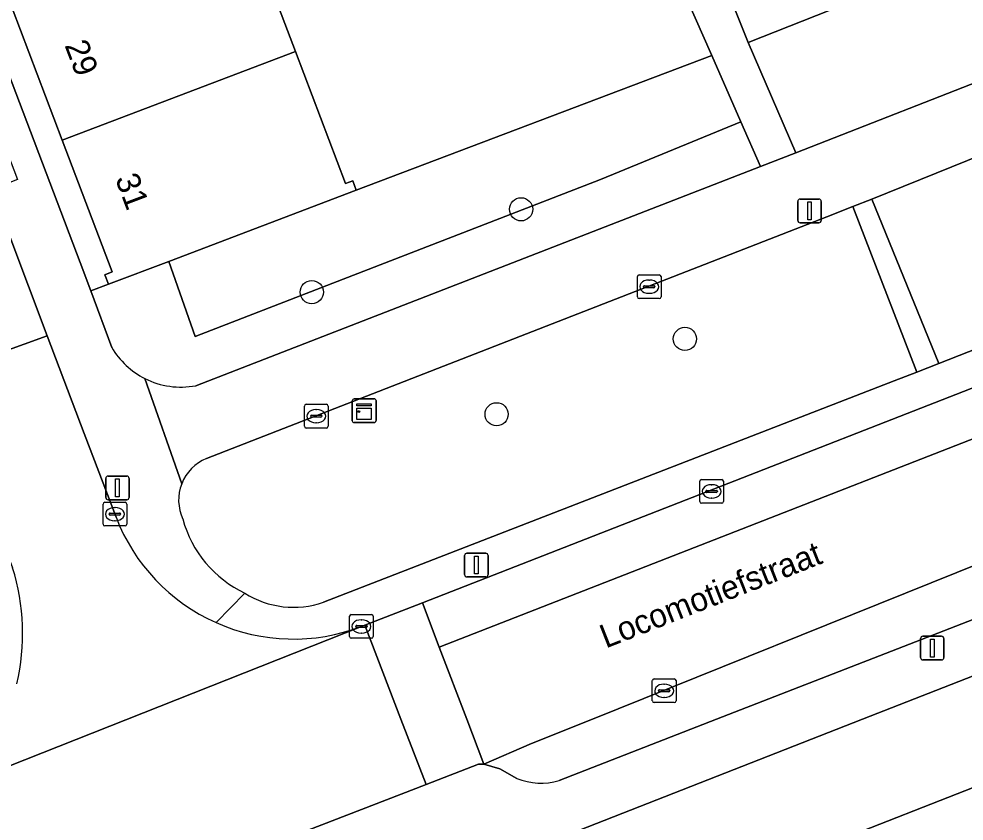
# Model space of a CAD drawing. Extents: x 162989 to 165008, y 383432 to 384338.
# Drawn here: x 163944.51 to 163984.37, y 383995.71 to 384029.53 of the extents above; entities that cross this region are included whole.
import ezdxf

# ---------------------------------------------------------------- set-up
doc = ezdxf.new("R2010")
doc.units = 0
for name, color, linetype in [('IMGEO_Boom', 7, 'Continuous'), ('IMGEO_Erf', 7, 'Continuous'), ('IMGEO_Groenvoorziening', 7, 'Continuous'), ('IMGEO_Kast', 7, 'Continuous'), ('IMGEO_Kolk', 7, 'Continuous'), ('IMGEO_Lichtmast', 7, 'Continuous'), ('IMGEO_Openbare_ruimte_label', 7, 'Continuous'), ('IMGEO_Pand', 7, 'Continuous'), ('IMGEO_Pand_nummerreeks', 7, 'Continuous'), ('IMGEO_Parkeervlak_open', 7, 'Continuous'), ('IMGEO_Rijbaan_lokaal_open', 7, 'Continuous'), ('IMGEO_Voetpad_open', 7, 'Continuous')]:
    doc.layers.add(name, color=color, linetype=linetype)

msp = doc.modelspace()

# ---------------------------------------------------------------- linework, layer by layer
at = {"layer": 'IMGEO_Boom'}
for centre in [(163965.69, 384021.504), (163956.864, 384018.013), (163972.597, 384016.041), (163964.657, 384012.862)]:
    msp.add_circle(centre, 0.489, dxfattribs=at)
at = {"layer": 'IMGEO_Erf'}
for points in [[(163943.537, 384061.532), (163945.643, 384055.968), (163947.749, 384050.405), (163949.856, 384044.841), (163951.962, 384039.278), (163954.068, 384033.715), (163956.175, 384028.151), (163958.279, 384022.593), (163958.588, 384022.709), (163958.74, 384022.307), (163973.729, 384027.989), (163972.384, 384031.053), (163969.628, 384036.532), (163967.145, 384041.315), (163965.004, 384045.848), (163957.177, 384062.593), (163954.16, 384068.424), (163952.82, 384071.014), (163951.255, 384074.041), (163946.04, 384085.093), (163944.693, 384087.722), (163943.187, 384090.664)], [(163932.033, 384058.943), (163947.096, 384019.256), (163947.541, 384018.062), (163948.288, 384018.345), (163948.138, 384018.748), (163948.445, 384018.863), (163946.338, 384024.426), (163944.232, 384029.99)], [(164010.509, 384011.664), (164000, 384007.793), (163980.091, 384000), (163962.348, 383993.055), (163960.87, 383992.07)], [(163960.66, 383990.018), (163961.435, 383987.966), (163967.123, 383990.2), (163973.139, 383992.563), (163978.985, 383994.86), (163984.797, 383997.143), (163990.831, 383999.513), (163992.07, 384000), (163996.693, 384001.816), (164000, 384003.115), (164002.477, 384004.075), (164008.327, 384006.341), (164014.738, 384008.825), (164014.172, 384010.446)]]:
    msp.add_lwpolyline(points, dxfattribs=at)
msp.add_lwpolyline([(163995.874, 384031.308), (163992.218, 384040.299), (163991.312, 384039.94), (163993.038, 384035.589), (163986.845, 384033.132), (163981.036, 384030.827), (163975.26, 384028.535), (163977.276, 384023.891), (163986.262, 384027.399)], close=True, dxfattribs=at)
at = {"layer": 'IMGEO_Groenvoorziening'}
for points in [[(163974.955, 384025.194), (163973.729, 384027.989), (163958.74, 384022.307), (163950.832, 384019.309), (163951.951, 384016.142), (163969.036, 384022.762)], [(163994.981, 384027.789), (163994.701, 384027.673), (163980.488, 384021.938), (163983.3, 384015), (163997.388, 384020.537), (163997.779, 384020.691)]]:
    msp.add_lwpolyline(points, close=True, dxfattribs=at)
for points in [[(163951.966, 384014.066), (163975.782, 384023.308), (163974.955, 384025.194), (163969.036, 384022.762), (163951.951, 384016.142), (163950.832, 384019.309)], [(163981.426, 384014.275), (163982.379, 384014.644), (163979.681, 384021.62), (163978.582, 384021.186), (163952.42, 384010.995)], [(163950.832, 384019.309), (163948.288, 384018.345), (163947.541, 384018.062), (163948.429, 384015.677)], [(163957.353, 384004.941), (163981.426, 384014.275)]]:
    msp.add_lwpolyline(points, dxfattribs=at)
for centre, radius, start, end in [((163951.344, 384017.387), 3.379, 210.3945, 243.2515), ((163951.342, 384017.383), 3.375, 243.251, 280.6535), ((163953.155, 384009.236), 1.907, 112.6714, 158.5818), ((163953.158, 384009.235), 1.91, 158.6017, 204.4051), ((163956.116, 384009.726), 4.868, 195.2427, 244.7463), ((163956.086, 384008.512), 3.789, 237.3085, 289.5408)]:
    msp.add_arc(centre, radius, start, end, dxfattribs=at)
at = {"layer": 'IMGEO_Kast'}
for p, q in [((163958.647, 384013.511), (163959.488, 384013.511)), ((163959.488, 384013.511), (163958.647, 384013.511)), ((163958.572, 384012.586), (163958.572, 384013.427)), ((163958.572, 384013.427), (163958.572, 384012.586)), ((163959.572, 384013.436), (163959.572, 384012.595)), ((163959.572, 384012.595), (163959.572, 384013.436)), ((163959.497, 384012.511), (163958.656, 384012.511)), ((163958.656, 384012.511), (163959.497, 384012.511))]:
    msp.add_line(p, q, dxfattribs=at)
for points in [[(163958.767, 384013.301), (163959.367, 384013.301), (163959.367, 384013.216), (163958.767, 384013.216), (163958.767, 384013.301)], [(163958.767, 384013.126), (163959.367, 384013.126), (163959.367, 384012.637), (163958.767, 384012.637), (163958.767, 384013.126)]]:
    msp.add_lwpolyline(points, dxfattribs=at)
msp.add_circle((163958.851, 384012.975), 0.0377, dxfattribs=at)
for centre, start, end in [((163958.65, 384013.433), 92.4484, 184.2845), ((163958.65, 384013.433), 92.4484, 184.2845), ((163959.494, 384013.433), 2.4484, 94.2845), ((163959.494, 384013.433), 2.4484, 94.2845), ((163958.65, 384012.589), 182.4484, 274.2845), ((163958.65, 384012.589), 182.4484, 274.2845), ((163959.494, 384012.589), 272.4484, 4.2845), ((163959.494, 384012.589), 272.4484, 4.2845)]:
    msp.add_arc(centre, 0.0779, start, end, dxfattribs=at)
at = {"layer": 'IMGEO_Kolk'}
for p, q in [((163970.667, 384018.741), (163971.519, 384018.741)), ((163970.592, 384017.815), (163970.592, 384018.667)), ((163971.08, 384018.521), (163971.105, 384018.521)), ((163971.593, 384018.667), (163971.593, 384017.815)), ((163970.851, 384018.235), (163970.851, 384018.247)), ((163971.289, 384018.198), (163970.891, 384018.198)), ((163970.894, 384018.284), (163971.292, 384018.284)), ((163971.103, 384017.961), (163971.078, 384017.961)), ((163971.335, 384018.247), (163971.335, 384018.235)), ((163971.519, 384017.741), (163970.667, 384017.741)), ((163956.552, 384012.355), (163956.552, 384013.207)), ((163956.627, 384013.281), (163957.479, 384013.281)), ((163957.553, 384013.207), (163957.553, 384012.355)), ((163956.811, 384012.775), (163956.811, 384012.787)), ((163957.249, 384012.738), (163956.851, 384012.738)), ((163956.854, 384012.824), (163957.252, 384012.824)), ((163957.04, 384013.061), (163957.065, 384013.061)), ((163957.295, 384012.787), (163957.295, 384012.775)), ((163957.063, 384012.501), (163957.038, 384012.501)), ((163957.479, 384012.281), (163956.627, 384012.281)), ((163973.224, 384009.185), (163973.224, 384010.037)), ((163973.299, 384010.111), (163974.151, 384010.111)), ((163974.225, 384010.037), (163974.225, 384009.185)), ((163973.483, 384009.605), (163973.483, 384009.617)), ((163973.921, 384009.568), (163973.523, 384009.568)), ((163973.526, 384009.654), (163973.924, 384009.654)), ((163973.712, 384009.891), (163973.737, 384009.891)), ((163973.967, 384009.617), (163973.967, 384009.605)), ((163948.134, 384009.152), (163948.986, 384009.152)), ((163973.735, 384009.331), (163973.71, 384009.331)), ((163948.059, 384008.226), (163948.059, 384009.078)), ((163948.547, 384008.932), (163948.572, 384008.932)), ((163949.06, 384009.078), (163949.06, 384008.226)), ((163974.151, 384009.111), (163973.299, 384009.111)), ((163948.318, 384008.646), (163948.318, 384008.658)), ((163948.756, 384008.609), (163948.358, 384008.609)), ((163948.361, 384008.695), (163948.759, 384008.695)), ((163948.57, 384008.372), (163948.545, 384008.372)), ((163948.802, 384008.658), (163948.802, 384008.646)), ((163948.986, 384008.152), (163948.134, 384008.152)), ((163958.455, 384003.491), (163958.455, 384004.343)), ((163958.53, 384004.417), (163959.382, 384004.417)), ((163959.456, 384004.343), (163959.456, 384003.491)), ((163958.757, 384003.96), (163959.155, 384003.96)), ((163958.943, 384004.197), (163958.968, 384004.197)), ((163958.714, 384003.911), (163958.714, 384003.923)), ((163959.152, 384003.874), (163958.754, 384003.874)), ((163958.966, 384003.637), (163958.941, 384003.637)), ((163959.198, 384003.923), (163959.198, 384003.911)), ((163959.382, 384003.417), (163958.53, 384003.417)), ((163971.224, 384000.778), (163971.224, 384001.63)), ((163971.299, 384001.704), (163972.151, 384001.704)), ((163972.225, 384001.63), (163972.225, 384000.778)), ((163971.483, 384001.198), (163971.483, 384001.21)), ((163971.921, 384001.161), (163971.523, 384001.161)), ((163971.526, 384001.247), (163971.924, 384001.247)), ((163971.712, 384001.484), (163971.737, 384001.484)), ((163971.967, 384001.21), (163971.967, 384001.198)), ((163971.735, 384000.924), (163971.71, 384000.924)), ((163972.151, 384000.704), (163971.299, 384000.704))]:
    msp.add_line(p, q, dxfattribs=at)
for points in [[(163970.667, 384018.741), (163971.519, 384018.741)], [(163970.592, 384017.815), (163970.592, 384018.667)], [(163971.593, 384018.667), (163971.593, 384017.815)], [(163971.519, 384017.741), (163970.667, 384017.741)], [(163956.552, 384012.355), (163956.552, 384013.207)], [(163956.627, 384013.281), (163957.479, 384013.281)], [(163957.553, 384013.207), (163957.553, 384012.355)], [(163957.479, 384012.281), (163956.627, 384012.281)], [(163973.224, 384009.185), (163973.224, 384010.037)], [(163973.299, 384010.111), (163974.151, 384010.111)], [(163974.225, 384010.037), (163974.225, 384009.185)], [(163948.134, 384009.152), (163948.986, 384009.152)], [(163948.059, 384008.226), (163948.059, 384009.078)], [(163949.06, 384009.078), (163949.06, 384008.226)], [(163974.151, 384009.111), (163973.299, 384009.111)], [(163948.986, 384008.152), (163948.134, 384008.152)], [(163958.455, 384003.491), (163958.455, 384004.343)], [(163958.53, 384004.417), (163959.382, 384004.417)], [(163959.456, 384004.343), (163959.456, 384003.491)], [(163959.382, 384003.417), (163958.53, 384003.417)], [(163971.224, 384000.778), (163971.224, 384001.63)], [(163971.299, 384001.704), (163972.151, 384001.704)], [(163972.225, 384001.63), (163972.225, 384000.778)], [(163972.151, 384000.704), (163971.299, 384000.704)]]:
    msp.add_lwpolyline(points, dxfattribs=at)
for centre, radius, start, end in [((163970.669, 384018.665), 0.0765, 91.552, 178.448), ((163970.669, 384018.665), 0.0765, 91.552, 178.448), ((163971.517, 384018.665), 0.0765, 1.552, 88.448), ((163971.517, 384018.665), 0.0765, 1.552, 88.448), ((163970.891, 384018.244), 0.0403, 85.8775, 175.7526), ((163970.888, 384018.234), 0.0366, 178.938, 274.7102), ((163971.292, 384018.241), 0.043, 264.8664, 352.4533), ((163971.296, 384018.246), 0.0386, 1.7309, 96.639), ((163970.669, 384017.817), 0.0765, 181.552, 268.448), ((163970.669, 384017.817), 0.0765, 181.552, 268.448), ((163971.517, 384017.817), 0.0765, 271.552, 358.448), ((163971.517, 384017.817), 0.0765, 271.552, 358.448), ((163956.629, 384013.205), 0.0765, 91.552, 178.448), ((163956.629, 384013.205), 0.0765, 91.552, 178.448), ((163957.477, 384013.205), 0.0765, 1.552, 88.448), ((163957.477, 384013.205), 0.0765, 1.552, 88.448), ((163956.851, 384012.784), 0.0403, 85.8775, 175.7526), ((163956.848, 384012.774), 0.0366, 178.938, 274.7102), ((163957.252, 384012.781), 0.043, 264.8664, 352.4533), ((163957.256, 384012.786), 0.0386, 1.7309, 96.639), ((163956.629, 384012.357), 0.0765, 181.552, 268.448), ((163956.629, 384012.357), 0.0765, 181.552, 268.448), ((163957.477, 384012.357), 0.0765, 271.552, 358.448), ((163957.477, 384012.357), 0.0765, 271.552, 358.448), ((163973.301, 384010.035), 0.0765, 91.552, 178.448), ((163973.301, 384010.035), 0.0765, 91.552, 178.448), ((163974.149, 384010.035), 0.0765, 1.552, 88.448), ((163974.149, 384010.035), 0.0765, 1.552, 88.448), ((163973.523, 384009.614), 0.0403, 85.8775, 175.7526), ((163973.52, 384009.604), 0.0366, 178.938, 274.7102), ((163973.924, 384009.611), 0.043, 264.8664, 352.4533), ((163973.928, 384009.616), 0.0386, 1.7309, 96.639), ((163948.136, 384009.076), 0.0765, 91.552, 178.448), ((163948.136, 384009.076), 0.0765, 91.552, 178.448), ((163948.984, 384009.076), 0.0765, 1.552, 88.448), ((163948.984, 384009.076), 0.0765, 1.552, 88.448), ((163973.301, 384009.187), 0.0765, 181.552, 268.448), ((163973.301, 384009.187), 0.0765, 181.552, 268.448), ((163974.149, 384009.187), 0.0765, 271.552, 358.448), ((163974.149, 384009.187), 0.0765, 271.552, 358.448), ((163948.358, 384008.655), 0.0403, 85.8775, 175.7526), ((163948.355, 384008.645), 0.0366, 178.938, 274.7102), ((163948.759, 384008.652), 0.043, 264.8664, 352.4533), ((163948.763, 384008.657), 0.0386, 1.7309, 96.639), ((163948.136, 384008.228), 0.0765, 181.552, 268.448), ((163948.136, 384008.228), 0.0765, 181.552, 268.448), ((163948.984, 384008.228), 0.0765, 271.552, 358.448), ((163948.984, 384008.228), 0.0765, 271.552, 358.448), ((163958.532, 384004.341), 0.0765, 91.552, 178.448), ((163958.532, 384004.341), 0.0765, 91.552, 178.448), ((163959.38, 384004.341), 0.0765, 1.552, 88.448), ((163959.38, 384004.341), 0.0765, 1.552, 88.448), ((163958.754, 384003.92), 0.0403, 85.8775, 175.7526), ((163959.159, 384003.922), 0.0386, 1.7309, 96.639), ((163958.751, 384003.91), 0.0366, 178.938, 274.7102), ((163959.155, 384003.917), 0.043, 264.8664, 352.4533), ((163958.532, 384003.493), 0.0765, 181.552, 268.448), ((163958.532, 384003.493), 0.0765, 181.552, 268.448), ((163959.38, 384003.493), 0.0765, 271.552, 358.448), ((163959.38, 384003.493), 0.0765, 271.552, 358.448), ((163971.301, 384001.628), 0.0765, 91.552, 178.448), ((163971.301, 384001.628), 0.0765, 91.552, 178.448), ((163972.149, 384001.628), 0.0765, 1.552, 88.448), ((163972.149, 384001.628), 0.0765, 1.552, 88.448), ((163971.523, 384001.207), 0.0403, 85.8775, 175.7526), ((163971.52, 384001.197), 0.0366, 178.938, 274.7102), ((163971.924, 384001.204), 0.043, 264.8664, 352.4533), ((163971.928, 384001.209), 0.0386, 1.7309, 96.639), ((163971.301, 384000.78), 0.0765, 181.552, 268.448), ((163971.301, 384000.78), 0.0765, 181.552, 268.448), ((163972.149, 384000.78), 0.0765, 271.552, 358.448), ((163972.149, 384000.78), 0.0765, 271.552, 358.448)]:
    msp.add_arc(centre, radius, start, end, dxfattribs=at)
for centre, major_axis, ratio, start_param, end_param in [((163971.079, 384018.241), (-0.387, 0.002), 0.722429, 4.712389, 7.853982), ((163971.104, 384018.241), (-0.39, 0.002), 0.717154, 1.570796, 4.712389), ((163957.039, 384012.781), (-0.387, 0.002), 0.722429, 4.712389, 7.853982), ((163957.064, 384012.781), (-0.39, 0.002), 0.717154, 1.570796, 4.712389), ((163973.711, 384009.611), (-0.387, 0.002), 0.722429, 4.712389, 7.853982), ((163973.736, 384009.611), (-0.39, 0.002), 0.717154, 1.570796, 4.712389), ((163948.546, 384008.652), (-0.387, 0.002), 0.722429, 4.712389, 7.853982), ((163948.571, 384008.652), (-0.39, 0.002), 0.717154, 1.570796, 4.712389), ((163958.942, 384003.917), (-0.387, 0.002), 0.722429, 4.712389, 7.853982), ((163958.967, 384003.917), (-0.39, 0.002), 0.717154, 1.570796, 4.712389), ((163971.711, 384001.204), (-0.387, 0.002), 0.722429, 4.712389, 7.853982), ((163971.736, 384001.204), (-0.39, 0.002), 0.717154, 1.570796, 4.712389)]:
    msp.add_ellipse(centre, major_axis=major_axis, ratio=ratio, start_param=start_param, end_param=end_param, dxfattribs=at)
at = {"layer": 'IMGEO_Lichtmast'}
for p, q in [((163977.456, 384021.938), (163978.246, 384021.938)), ((163978.246, 384021.938), (163977.456, 384021.938)), ((163977.356, 384021.038), (163977.356, 384021.838)), ((163977.356, 384021.838), (163977.356, 384021.038)), ((163978.346, 384021.838), (163978.346, 384021.038)), ((163978.346, 384021.038), (163978.346, 384021.838)), ((163978.246, 384020.938), (163977.456, 384020.938)), ((163977.456, 384020.938), (163978.246, 384020.938)), ((163948.172, 384009.358), (163948.172, 384010.158)), ((163948.172, 384010.158), (163948.172, 384009.358)), ((163948.272, 384010.258), (163949.062, 384010.258)), ((163949.062, 384010.258), (163948.272, 384010.258)), ((163949.162, 384010.158), (163949.162, 384009.358)), ((163949.162, 384009.358), (163949.162, 384010.158)), ((163949.062, 384009.258), (163948.272, 384009.258)), ((163948.272, 384009.258), (163949.062, 384009.258)), ((163963.308, 384006.103), (163963.308, 384006.903)), ((163963.308, 384006.903), (163963.308, 384006.103)), ((163963.408, 384007.003), (163964.198, 384007.003)), ((163964.198, 384007.003), (163963.408, 384007.003)), ((163964.298, 384006.903), (163964.298, 384006.103)), ((163964.298, 384006.103), (163964.298, 384006.903)), ((163964.198, 384006.003), (163963.408, 384006.003)), ((163963.408, 384006.003), (163964.198, 384006.003)), ((163982.534, 384002.602), (163982.534, 384003.402)), ((163982.534, 384003.402), (163982.534, 384002.602)), ((163982.634, 384003.502), (163983.424, 384003.502)), ((163983.424, 384003.502), (163982.634, 384003.502)), ((163983.524, 384003.402), (163983.524, 384002.602)), ((163983.524, 384002.602), (163983.524, 384003.402)), ((163983.424, 384002.502), (163982.634, 384002.502)), ((163982.634, 384002.502), (163983.424, 384002.502))]:
    msp.add_line(p, q, dxfattribs=at)
for points in [[(163977.776, 384021.813), (163977.926, 384021.813), (163977.926, 384021.063), (163977.776, 384021.063), (163977.776, 384021.813)], [(163948.592, 384010.133), (163948.742, 384010.133), (163948.742, 384009.383), (163948.592, 384009.383), (163948.592, 384010.133)], [(163963.728, 384006.878), (163963.878, 384006.878), (163963.878, 384006.128), (163963.728, 384006.128), (163963.728, 384006.878)], [(163982.954, 384003.377), (163983.104, 384003.377), (163983.104, 384002.627), (163982.954, 384002.627), (163982.954, 384003.377)]]:
    msp.add_lwpolyline(points, dxfattribs=at)
for centre, start, end in [((163977.456, 384021.838), 90, 180), ((163977.456, 384021.838), 90, 180), ((163978.246, 384021.838), 0, 90), ((163978.246, 384021.838), 360, 90), ((163977.456, 384021.038), 180, 270), ((163977.456, 384021.038), 180, 270), ((163978.246, 384021.038), 270, 0), ((163978.246, 384021.038), 270, 0), ((163948.272, 384010.158), 90, 180), ((163948.272, 384010.158), 90, 180), ((163949.062, 384010.158), 0, 90), ((163949.062, 384010.158), 360, 90), ((163948.272, 384009.358), 180, 270), ((163948.272, 384009.358), 180, 270), ((163949.062, 384009.358), 270, 0), ((163949.062, 384009.358), 270, 0), ((163963.408, 384006.903), 90, 180), ((163963.408, 384006.903), 90, 180), ((163964.198, 384006.903), 0, 90), ((163964.198, 384006.903), 360, 90), ((163963.408, 384006.103), 180, 270), ((163963.408, 384006.103), 180, 270), ((163964.198, 384006.103), 270, 0), ((163964.198, 384006.103), 270, 0), ((163982.634, 384003.402), 90, 180), ((163982.634, 384003.402), 90, 180), ((163983.424, 384003.402), 0, 90), ((163983.424, 384003.402), 360, 90), ((163982.634, 384002.602), 180, 270), ((163982.634, 384002.602), 180, 270), ((163983.424, 384002.602), 270, 0), ((163983.424, 384002.602), 270, 0)]:
    msp.add_arc(centre, 0.1, start, end, dxfattribs=at)
at = {"layer": 'IMGEO_Pand'}
for points in [[(163979.306, 384035.177), (163980.216, 384035.537), (163978.83, 384039.023), (163973.149, 384036.769), (163974.347, 384033.684), (163973.37, 384033.297), (163973.415, 384033.183), (163973.58, 384032.767), (163975.26, 384028.535), (163981.036, 384030.827)], [(163954.068, 384033.715), (163944.232, 384029.99), (163946.338, 384024.426), (163956.175, 384028.151)], [(163958.74, 384022.307), (163958.588, 384022.709), (163958.279, 384022.593), (163956.175, 384028.151), (163946.338, 384024.426), (163948.445, 384018.863), (163948.138, 384018.748), (163948.288, 384018.345), (163950.832, 384019.309)], [(163986.982, 383988.873), (163985.597, 383992.392), (163986.522, 383992.752), (163984.797, 383997.143), (163978.985, 383994.86), (163980.71, 383990.469), (163979.785, 383990.109), (163981.17, 383986.59)]]:
    msp.add_lwpolyline(points, close=True, dxfattribs=at)
at = {"layer": 'IMGEO_Parkeervlak_open'}
msp.add_lwpolyline([(163997.677, 384016.87), (163996.947, 384018.74), (163961.527, 384004.918), (163962.239, 384003.048)], close=True, dxfattribs=at)
for points in [[(164009.791, 384016.228), (164002.191, 384013.414), (164000, 384012.603), (163999.431, 384012.374), (163968.705, 384000), (163966.134, 383998.974), (163964.117, 383998.113), (163964.798, 383997.915), (163965.51, 383997.511)], [(163967.3, 383997.416), (163973.932, 384000), (164006.927, 384012.829)]]:
    msp.add_lwpolyline(points, dxfattribs=at)
msp.add_arc((163966.539, 383999.996), 2.69, 247.4989, 286.4251, dxfattribs=at)
at = {"layer": 'IMGEO_Rijbaan_lokaal_open'}
for points in [[(163902.699, 384136.428), (163902.42, 384136.156), (163900.713, 384134.073), (163899.073, 384131.221), (163898.552, 384127.219), (163903.65, 384113.577), (163905.658, 384108.202), (163908.244, 384101.283), (163909.453, 384098.047), (163932.403, 384037.527), (163941.155, 384014.522), (163945.705, 384016.169), (163943.363, 384022.339), (163928.089, 384062.572), (163925.404, 384069.644), (163909.585, 384111.313)], [(163948.608, 384008.523), (163947.266, 384012.058), (163945.705, 384016.169), (163941.155, 384014.522), (163943.847, 384007.446), (163944.247, 384006.394)], [(163941.227, 383996.897), (163958.953, 384003.914)]]:
    msp.add_lwpolyline(points, dxfattribs=at)
for points in [[(163999.431, 384012.374), (163997.677, 384016.87), (163962.239, 384003.048), (163963.399, 384000), (163964.117, 383998.113), (163966.134, 383998.974), (163968.705, 384000)], [(163962.239, 384003.048), (163961.527, 384004.918), (163959.093, 384003.969), (163960.624, 384000), (163961.684, 383997.251), (163963.895, 383998.107), (163963.995, 383998.11), (163964.117, 383998.113), (163963.399, 384000)], [(163961.684, 383997.251), (163960.624, 384000), (163959.093, 384003.969), (163958.953, 384003.914), (163941.227, 383996.897), (163940.738, 383996.695), (163943.426, 383990.186), (163947.029, 383991.58), (163950.595, 383992.96)]]:
    msp.add_lwpolyline(points, close=True, dxfattribs=at)
for centre, radius, start, end in [((163956.087, 384011.393), 8.011, 200.9936, 245.9786), ((163935.211, 384003.609), 9.455, 347.1054, 17.1298), ((163956.085, 384011.396), 8.012, 245.9983, 290.9726)]:
    msp.add_arc(centre, radius, start, end, dxfattribs=at)
at = {"layer": 'IMGEO_Voetpad_open'}
for points in [[(163932.033, 384058.943), (163917.32, 384097.768), (163911.891, 384112.19), (163910.739, 384111.752), (163916.167, 384097.33), (163926.518, 384070.073), (163925.404, 384069.644), (163928.089, 384062.572), (163929.171, 384062.968), (163944.456, 384022.755), (163943.363, 384022.339), (163945.705, 384016.169), (163947.266, 384012.058), (163948.608, 384008.523)], [(163948.429, 384015.677), (163947.541, 384018.062), (163947.096, 384019.256), (163932.033, 384058.943)], [(164011.763, 384037.395), (164000, 384032.665), (163999.627, 384032.516), (163999.514, 384032.788), (163997.261, 384031.872), (163997.241, 384031.864), (163995.874, 384031.308), (163986.262, 384027.399), (163977.276, 384023.891), (163975.782, 384023.308), (163951.966, 384014.066)], [(163972.384, 384031.053), (163973.729, 384027.989), (163974.955, 384025.194), (163975.782, 384023.308), (163977.276, 384023.891), (163975.26, 384028.535), (163973.58, 384032.767)], [(163952.42, 384010.995), (163978.582, 384021.186), (163979.681, 384021.62), (163980.488, 384021.938), (163994.701, 384027.673)], [(164003.995, 384023.133), (164000, 384021.568), (163999.288, 384021.286), (163999.076, 384021.203), (163997.779, 384020.691), (163997.388, 384020.537), (163983.3, 384015), (163982.379, 384014.644), (163981.426, 384014.275), (163957.353, 384004.941)], [(163958.953, 384003.914), (163959.093, 384003.969), (163961.527, 384004.918), (163996.947, 384018.74)], [(163951.38, 384009.932), (163949.823, 384014.369)], [(163949.823, 384014.369), (163951.38, 384009.932)], [(164006.927, 384012.829), (163973.932, 384000), (163967.3, 383997.416)], [(163980.091, 384000), (164000, 384007.793), (164010.509, 384011.664)], [(163954.039, 384005.323), (163952.826, 384004.076)], [(163952.826, 384004.076), (163954.039, 384005.323)], [(163867.106, 383954.34), (163868.264, 383955.232), (163901.539, 383968.747), (163901.64, 383968.618), (163918.144, 383975.149), (163941.789, 383984.802), (163952.554, 383989.112), (163962.348, 383993.055), (163980.091, 384000)], [(163965.51, 383997.511), (163964.798, 383997.915), (163964.117, 383998.113), (163963.995, 383998.11), (163963.895, 383998.107), (163961.684, 383997.251), (163950.595, 383992.96), (163950.775, 383992.495), (163947.209, 383991.114), (163947.029, 383991.58), (163943.426, 383990.186), (163943.33, 383990.107)]]:
    msp.add_lwpolyline(points, dxfattribs=at)
msp.add_lwpolyline([(163980.488, 384021.938), (163979.681, 384021.62), (163982.379, 384014.644), (163983.3, 384015)], close=True, dxfattribs=at)
for centre, radius, start, end in [((163951.344, 384017.387), 3.379, 210.3945, 243.2515), ((163951.342, 384017.383), 3.375, 243.251, 280.6535), ((163953.155, 384009.236), 1.907, 112.6714, 158.5818), ((163953.158, 384009.235), 1.91, 158.6017, 204.4051), ((163956.087, 384011.393), 8.011, 200.9936, 245.9786), ((163956.116, 384009.726), 4.868, 195.2427, 244.7463), ((163935.211, 384003.609), 9.455, 347.1054, 17.1298), ((163956.086, 384008.512), 3.789, 237.3085, 289.5408), ((163956.085, 384011.396), 8.012, 245.9983, 290.9726), ((163966.539, 383999.996), 2.69, 247.4989, 286.4251)]:
    msp.add_arc(centre, radius, start, end, dxfattribs=at)

# ---------------------------------------------------------------- texts
at = {"layer": 'IMGEO_Openbare_ruimte_label'}
msp.add_text('Locomotiefstraat', height=1, rotation=21.4611, dxfattribs=at).set_placement((163969.261, 384002.982))
at = {"layer": 'IMGEO_Pand_nummerreeks'}
for s, p in [('29', (163946.428, 384028.424)), ('31', (163948.559, 384022.795))]:
    msp.add_text(s, height=1, rotation=290.7409, dxfattribs=at).set_placement(p)

doc.saveas('drawing.dxf')
